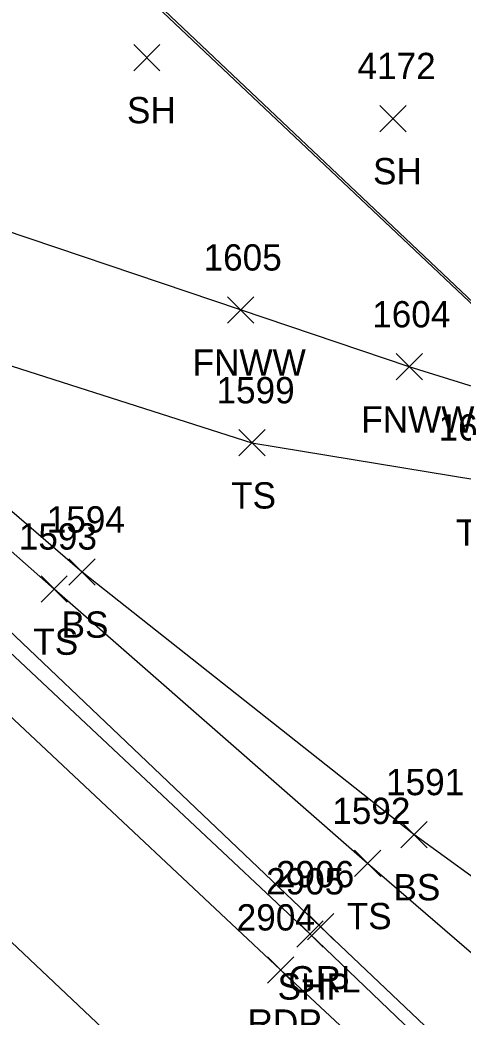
# Model space of a CAD drawing. Extents: x 1647574 to 1652703, y 212895 to 228670.
# Drawn here: x 1649146.1 to 1649179.8, y 226954.6 to 227030.4 of the extents above; entities that cross this region are included whole.
import ezdxf

# ---------------------------------------------------------------- set-up
doc = ezdxf.new("R2010")
doc.units = 0
for name, color, linetype in [('BDC', 7, 'Continuous'), ('L_A', 7, 'Continuous'), ('L_I', 7, 'Continuous'), ('L_TIC', 7, 'Continuous'), ('LELB', 7, 'Continuous'), ('LFNC', 7, 'Continuous'), ('P_A', 7, 'Continuous'), ('P_I', 7, 'Continuous'), ('P_TIC', 7, 'Continuous'), ('PET', 7, 'Continuous'), ('PRC', 7, 'Continuous'), ('PSP', 7, 'Continuous'), ('R_A', 7, 'Continuous'), ('R_I', 7, 'Continuous'), ('R_TIC', 7, 'Continuous'), ('RGR', 7, 'Continuous')]:
    doc.layers.add(name, color=color, linetype=linetype)

msp = doc.modelspace()

# ---------------------------------------------------------------- linework, layer by layer
at = {"layer": 'BDC'}
for points in [[(1649190.777, 226999.084), (1649140.468, 227046.558), (1649090.33, 227093.733), (1649025.71, 227154.751), (1648968.186, 227208.898), (1648910.789, 227263.155), (1648860.431, 227310.794), (1648808.664, 227359.741)], [(1649190.944, 226999.114), (1649140.59, 227046.719), (1649090.397, 227093.864), (1649025.741, 227154.791), (1648968.355, 227208.988), (1648910.836, 227263.351), (1648860.59, 227310.809), (1648808.767, 227359.651)]]:
    msp.add_lwpolyline(points, dxfattribs=at)
at = {"layer": 'L_TIC'}
for points in [[(1649154.743, 227026.55), (1649156.743, 227028.55)], [(1649156.743, 227026.55), (1649154.743, 227028.55)], [(1649173.467, 227021.91), (1649175.467, 227023.91)], [(1649175.467, 227021.91), (1649173.467, 227023.91)], [(1649161.879, 227007.351), (1649163.879, 227009.351)], [(1649163.879, 227007.351), (1649161.879, 227009.351)], [(1649174.712, 227003.03), (1649176.712, 227005.03)], [(1649176.712, 227003.03), (1649174.712, 227005.03)], [(1649162.745, 226997.25), (1649164.745, 226999.25)], [(1649164.745, 226997.25), (1649162.745, 226999.25)], [(1649149.815, 226987.424), (1649151.815, 226989.424)], [(1649151.815, 226987.424), (1649149.815, 226989.424)], [(1649147.692, 226986.126), (1649149.692, 226988.126)], [(1649149.692, 226986.126), (1649147.692, 226988.126)], [(1649175.07, 226967.448), (1649177.07, 226969.448)], [(1649177.07, 226967.448), (1649175.07, 226969.448)], [(1649171.545, 226965.257), (1649173.545, 226967.257)], [(1649173.545, 226965.257), (1649171.545, 226967.257)]]:
    msp.add_lwpolyline(points, dxfattribs=at)
at = {"layer": 'LELB'}
for points in [[(1649601.717, 226556.302), (1649565.565, 226590.442), (1649531.933, 226623.516), (1649496.555, 226657.42), (1649463.007, 226688.129), (1649429.087, 226720.608), (1649397.934, 226750.553), (1649357.866, 226787.133), (1649324.24, 226819.114), (1649290.454, 226852.029), (1649264.596, 226876.987), (1649236.486, 226903.171), (1649212.259, 226932.025), (1649172.545, 226966.257), (1649148.692, 226987.126), (1649125.302, 227007.744), (1649116.811, 227012.433), (1649123.681, 227011.795), (1649139.116, 227006.117), (1649163.745, 226998.25), (1649180.85, 226995.424), (1649185.969, 226996.023), (1649188.097, 226997.429)], [(1649192.206, 226956.741), (1649176.07, 226968.448), (1649150.815, 226988.424), (1649123.681, 227011.795)]]:
    msp.add_lwpolyline(points, dxfattribs=at)
at = {"layer": 'LFNC'}
msp.add_lwpolyline([(1649183.632, 227001.567), (1649175.712, 227004.03), (1649162.879, 227008.351), (1649140.743, 227015.822), (1649121.817, 227022.228), (1649109.537, 227025.911), (1649101.581, 227028.294)], dxfattribs=at)
at = {"layer": 'P_TIC'}
for points in [[(1649167.155, 226959.901), (1649169.155, 226961.901)], [(1649169.155, 226959.901), (1649167.155, 226961.901)], [(1649164.919, 226957.157), (1649166.919, 226959.157)], [(1649166.919, 226957.157), (1649164.919, 226959.157)]]:
    msp.add_lwpolyline(points, dxfattribs=at)
at = {"layer": 'PET'}
msp.add_lwpolyline([(1649093.954, 227025.501), (1649126.979, 226994.683), (1649165.919, 226958.157), (1649194.973, 226931.06), (1649223.585, 226903.582), (1649259.384, 226869.94), (1649293.456, 226837.808), (1649328.565, 226805.248), (1649367.407, 226768.356), (1649403.389, 226734.5), (1649427.726, 226711.628), (1649463.626, 226677.531), (1649497.385, 226645.661), (1649535.816, 226609.256), (1649568.76, 226578.145), (1649602.842, 226545.717)], dxfattribs=at)
at = {"layer": 'PRC'}
msp.add_lwpolyline([(1649071.001, 227030.272), (1649097.265, 227005.125), (1649118.089, 226986.084), (1649157.008, 226949.333), (1649185.963, 226922.495), (1649216.077, 226894.126), (1649250.578, 226861.494), (1649285.588, 226828.843), (1649319.083, 226797.046), (1649359.189, 226759.473), (1649394.665, 226725.954), (1649419.603, 226702.042), (1649454.559, 226669.332), (1649489.14, 226637.081), (1649527.318, 226600.873), (1649559.914, 226569.961), (1649593.92, 226537.249)], dxfattribs=at)
at = {"layer": 'PSP'}
msp.add_lwpolyline([(1649099.962, 227024.603), (1649112.122, 227013.185), (1649129.857, 226996.806), (1649168.155, 226960.901), (1649197.391, 226932.91), (1649226.275, 226906.094), (1649262.025, 226872.712), (1649296.017, 226840.812), (1649331.67, 226807.621), (1649370.43, 226771.629), (1649405.772, 226737.702), (1649429.963, 226714.794), (1649466.374, 226680.161), (1649499.939, 226648.68), (1649538.119, 226612.037), (1649571.179, 226581.281), (1649605.622, 226548.463)], dxfattribs=at)
at = {"layer": 'R_TIC'}
for points in [[(1649167.969, 226960.448), (1649169.969, 226962.448)], [(1649169.969, 226960.448), (1649167.969, 226962.448)]]:
    msp.add_lwpolyline(points, dxfattribs=at)
at = {"layer": 'RGR'}
msp.add_lwpolyline([(1649113.636, 227012.863), (1649130.397, 226998.107), (1649168.969, 226961.448), (1649198.172, 226933.736)], dxfattribs=at)

# ---------------------------------------------------------------- texts
at = {"layer": 'L_A'}
for s, p in [('SH', (1649154.232, 227022.55)), ('SH', (1649172.955, 227017.91)), ('FNWW', (1649159.225, 227003.351)), ('FNWW', (1649172.058, 226999.03)), ('TS', (1649162.154, 226993.25)), ('TS', (1649179.26, 226990.424)), ('BS', (1649149.256, 226983.424)), ('TS', (1649147.102, 226982.126)), ('BS', (1649174.511, 226963.448)), ('TS', (1649170.955, 226961.257))]:
    msp.add_text(s, height=2, dxfattribs=at).set_placement(p)
at = {"layer": 'L_I'}
for s, p in [('4172', (1649171.774, 227025.91)), ('1605', (1649160.06, 227011.351)), ('1604', (1649172.893, 227007.03)), ('1599', (1649161.044, 227001.25)), ('1600', (1649177.945, 226998.424)), ('1594', (1649148.123, 226991.424)), ('1593', (1649146, 226990.126)), ('1591', (1649173.945, 226971.448)), ('1592', (1649169.852, 226969.257))]:
    msp.add_text(s, height=2, dxfattribs=at).set_placement(p)
at = {"layer": 'P_A'}
for s, p in [('SHP', (1649165.69, 226955.901)), ('RDP', (1649163.407, 226953.157))]:
    msp.add_text(s, height=2, dxfattribs=at).set_placement(p)
at = {"layer": 'P_I'}
for s, p in [('2905', (1649164.816, 226963.901)), ('2904', (1649162.58, 226961.157))]:
    msp.add_text(s, height=2, dxfattribs=at).set_placement(p)
at = {"layer": 'R_A'}
msp.add_text('GRL', height=2, dxfattribs=at).set_placement((1649166.512, 226956.448))
at = {"layer": 'R_I'}
msp.add_text('2906', height=2, dxfattribs=at).set_placement((1649165.575, 226964.448))

doc.saveas('drawing.dxf')
